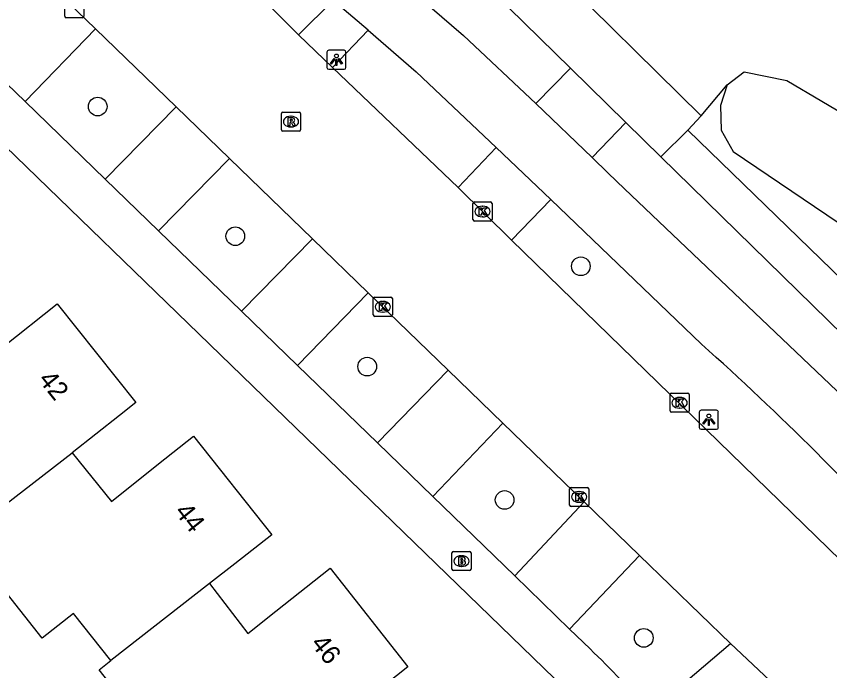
# Model space of a CAD drawing. Extents: x 157321 to 158827, y 386650 to 388532.
# Drawn here: x 157873.45 to 157916.06, y 387455 to 387489.28 of the extents above; entities that cross this region are included whole.
import ezdxf

# ---------------------------------------------------------------- set-up
doc = ezdxf.new("R2010")
doc.units = 0
for name, color, linetype in [('IMGEO_Boom', 7, 'Continuous'), ('IMGEO_Brandkraan', 7, 'Continuous'), ('IMGEO_Fietspad_gesloten', 7, 'Continuous'), ('IMGEO_Groenvoorziening', 7, 'Continuous'), ('IMGEO_Kolk', 7, 'Continuous'), ('IMGEO_Lichtpunt', 7, 'Continuous'), ('IMGEO_Loofbos', 7, 'Continuous'), ('IMGEO_Pand', 7, 'Continuous'), ('IMGEO_Pand_nummerreeks', 7, 'Continuous'), ('IMGEO_Parkeervlak_halfverhard', 7, 'Continuous'), ('IMGEO_Rijbaan_lokaal_gesloten', 7, 'Continuous'), ('IMGEO_Rioolput', 7, 'Continuous'), ('IMGEO_Voetpad_halfverhard', 7, 'Continuous'), ('IMGEO_Voetpad_open', 7, 'Continuous')]:
    doc.layers.add(name, color=color, linetype=linetype)

msp = doc.modelspace()

# ---------------------------------------------------------------- linework, layer by layer
at = {"layer": 'IMGEO_Boom'}
for centre in [(157877.711, 387484.548), (157884.92, 387477.758), (157903.019, 387476.182), (157891.829, 387470.927), (157899.026, 387463.943), (157906.315, 387456.717)]:
    msp.add_circle(centre, 0.489, dxfattribs=at)
at = {"layer": 'IMGEO_Brandkraan'}
for p, q in [((157896.265, 387460.317), (157896.265, 387461.169)), ((157896.34, 387461.243), (157897.192, 387461.243)), ((157896.753, 387461.023), (157896.778, 387461.023)), ((157897.266, 387461.169), (157897.266, 387460.317)), ((157896.776, 387460.463), (157896.751, 387460.463)), ((157897.192, 387460.243), (157896.34, 387460.243))]:
    msp.add_line(p, q, dxfattribs=at)
for points in [[(157896.265, 387460.317), (157896.265, 387461.169)], [(157896.34, 387461.243), (157897.192, 387461.243)], [(157896.613, 387460.943), (157896.613, 387460.543), (157896.826, 387460.543)], [(157896.844, 387460.943), (157896.613, 387460.943)], [(157896.792, 387460.862), (157896.738, 387460.862), (157896.738, 387460.786)], [(157897.266, 387461.169), (157897.266, 387460.317)], [(157896.738, 387460.786), (157896.791, 387460.786)], [(157896.8, 387460.71), (157896.738, 387460.71), (157896.738, 387460.629)], [(157896.738, 387460.629), (157896.8, 387460.629)], [(157897.192, 387460.243), (157896.34, 387460.243)]]:
    msp.add_lwpolyline(points, dxfattribs=at)
for centre, radius, start, end in [((157896.342, 387461.167), 0.0765, 91.552, 178.448), ((157896.342, 387461.167), 0.0765, 91.552, 178.448), ((157896.793, 387460.824), 0.0379, 267.8285, 90.9355), ((157896.848, 387460.798), 0.145, 59.4692, 91.5367), ((157896.873, 387460.845), 0.0922, 285.5137, 58.1501), ((157897.19, 387461.167), 0.0765, 1.552, 88.448), ((157897.19, 387461.167), 0.0765, 1.552, 88.448), ((157896.801, 387460.669), 0.0404, 269.8759, 90.5077), ((157896.832, 387460.794), 0.251, 268.6676, 293.5347), ((157896.878, 387460.653), 0.105, 301.3115, 78.989), ((157896.342, 387460.319), 0.0765, 181.552, 268.448), ((157896.342, 387460.319), 0.0765, 181.552, 268.448), ((157897.19, 387460.319), 0.0765, 271.552, 358.448), ((157897.19, 387460.319), 0.0765, 271.552, 358.448)]:
    msp.add_arc(centre, radius, start, end, dxfattribs=at)
for centre, major_axis, ratio, start_param, end_param in [((157896.752, 387460.743), (-0.387, 0.002), 0.722429, 4.712389, 7.853982), ((157896.777, 387460.743), (-0.39, 0.002), 0.717154, 1.570796, 4.712389)]:
    msp.add_ellipse(centre, major_axis=major_axis, ratio=ratio, start_param=start_param, end_param=end_param, dxfattribs=at)
at = {"layer": 'IMGEO_Fietspad_gesloten'}
for points in [[(157892.213, 387492.301), (157896.869, 387488.269), (157900.667, 387484.7)], [(157891.885, 387488.557), (157890.054, 387490.107)], [(157891.885, 387488.557), (157894.388, 387486.371), (157898.584, 387482.4)], [(157903.608, 387481.886), (157900.667, 387484.7)], [(157898.584, 387482.4), (157900.016, 387481.039), (157901.446, 387479.676)], [(157903.608, 387481.886), (157904.457, 387481.066), (157905.305, 387480.243), (157917.516, 387468.634)], [(157909.34, 387472.1), (157901.446, 387479.676)]]:
    msp.add_lwpolyline(points, dxfattribs=at)
msp.add_arc((157807.404, 387357.992), 153.009, 42.05065, 48.2247, dxfattribs=at)
at = {"layer": 'IMGEO_Groenvoorziening'}
msp.add_lwpolyline([(157909.326, 387484.059), (157910.689, 387485.682)], dxfattribs=at)
at = {"layer": 'IMGEO_Kolk'}
for p, q in [((157875.988, 387489.277), (157875.988, 387490.129)), ((157876.989, 387490.129), (157876.989, 387489.277)), ((157876.915, 387489.203), (157876.063, 387489.203)), ((157897.367, 387478.625), (157897.367, 387479.477)), ((157897.442, 387479.551), (157898.294, 387479.551)), ((157897.855, 387479.331), (157897.88, 387479.331)), ((157898.368, 387479.477), (157898.368, 387478.625)), ((157897.878, 387478.771), (157897.853, 387478.771)), ((157898.294, 387478.551), (157897.442, 387478.551)), ((157892.146, 387473.634), (157892.146, 387474.486)), ((157892.221, 387474.56), (157893.073, 387474.56)), ((157893.147, 387474.486), (157893.147, 387473.634)), ((157892.634, 387474.34), (157892.659, 387474.34)), ((157892.657, 387473.78), (157892.632, 387473.78)), ((157893.073, 387473.56), (157892.221, 387473.56)), ((157907.691, 387468.607), (157907.691, 387469.459)), ((157907.766, 387469.533), (157908.618, 387469.533)), ((157908.692, 387469.459), (157908.692, 387468.607)), ((157908.179, 387469.313), (157908.204, 387469.313)), ((157908.618, 387468.533), (157907.766, 387468.533)), ((157908.202, 387468.753), (157908.177, 387468.753)), ((157902.429, 387463.676), (157902.429, 387464.528)), ((157902.504, 387464.602), (157903.356, 387464.602)), ((157902.917, 387464.382), (157902.942, 387464.382)), ((157903.43, 387464.528), (157903.43, 387463.676)), ((157902.94, 387463.822), (157902.915, 387463.822)), ((157903.356, 387463.602), (157902.504, 387463.602))]:
    msp.add_line(p, q, dxfattribs=at)
for points in [[(157875.988, 387489.277), (157875.988, 387490.129)], [(157876.989, 387490.129), (157876.989, 387489.277)], [(157876.915, 387489.203), (157876.063, 387489.203)], [(157897.367, 387478.625), (157897.367, 387479.477)], [(157897.442, 387479.551), (157898.294, 387479.551)], [(157897.688, 387479.251), (157897.811, 387479.251), (157897.811, 387479.1), (157897.941, 387479.251), (157898.105, 387479.251), (157897.959, 387479.1), (157898.112, 387478.851), (157897.96, 387478.851), (157897.875, 387479.015), (157897.811, 387478.948), (157897.811, 387478.851), (157897.688, 387478.851), (157897.688, 387479.251)], [(157898.368, 387479.477), (157898.368, 387478.625)], [(157898.294, 387478.551), (157897.442, 387478.551)], [(157892.146, 387473.634), (157892.146, 387474.486)], [(157892.221, 387474.56), (157893.073, 387474.56)], [(157893.147, 387474.486), (157893.147, 387473.634)], [(157892.467, 387474.26), (157892.59, 387474.26), (157892.59, 387474.109), (157892.72, 387474.26), (157892.884, 387474.26), (157892.738, 387474.109), (157892.891, 387473.86), (157892.739, 387473.86), (157892.654, 387474.024), (157892.59, 387473.957), (157892.59, 387473.86), (157892.467, 387473.86), (157892.467, 387474.26)], [(157893.073, 387473.56), (157892.221, 387473.56)], [(157907.691, 387468.607), (157907.691, 387469.459)], [(157907.766, 387469.533), (157908.618, 387469.533)], [(157908.692, 387469.459), (157908.692, 387468.607)], [(157908.012, 387469.233), (157908.135, 387469.233), (157908.135, 387469.082), (157908.265, 387469.233), (157908.429, 387469.233), (157908.283, 387469.082), (157908.436, 387468.833), (157908.284, 387468.833), (157908.199, 387468.997), (157908.135, 387468.93), (157908.135, 387468.833), (157908.012, 387468.833), (157908.012, 387469.233)], [(157908.618, 387468.533), (157907.766, 387468.533)], [(157902.429, 387463.676), (157902.429, 387464.528)], [(157902.504, 387464.602), (157903.356, 387464.602)], [(157902.75, 387464.302), (157902.873, 387464.302), (157902.873, 387464.151), (157903.003, 387464.302), (157903.167, 387464.302), (157903.021, 387464.151), (157903.174, 387463.902), (157903.022, 387463.902), (157902.937, 387464.066), (157902.873, 387463.999), (157902.873, 387463.902), (157902.75, 387463.902), (157902.75, 387464.302)], [(157903.43, 387464.528), (157903.43, 387463.676)], [(157903.356, 387463.602), (157902.504, 387463.602)]]:
    msp.add_lwpolyline(points, dxfattribs=at)
for centre, start, end in [((157876.065, 387489.279), 181.552, 268.448), ((157876.065, 387489.279), 181.552, 268.448), ((157876.913, 387489.279), 271.552, 358.448), ((157876.913, 387489.279), 271.552, 358.448), ((157897.444, 387479.475), 91.552, 178.448), ((157897.444, 387479.475), 91.552, 178.448), ((157898.292, 387479.475), 1.552, 88.448), ((157898.292, 387479.475), 1.552, 88.448), ((157897.444, 387478.627), 181.552, 268.448), ((157897.444, 387478.627), 181.552, 268.448), ((157898.292, 387478.627), 271.552, 358.448), ((157898.292, 387478.627), 271.552, 358.448), ((157892.223, 387474.484), 91.552, 178.448), ((157892.223, 387474.484), 91.552, 178.448), ((157893.071, 387474.484), 1.552, 88.448), ((157893.071, 387474.484), 1.552, 88.448), ((157892.223, 387473.636), 181.552, 268.448), ((157892.223, 387473.636), 181.552, 268.448), ((157893.071, 387473.636), 271.552, 358.448), ((157893.071, 387473.636), 271.552, 358.448), ((157907.768, 387469.457), 91.552, 178.448), ((157907.768, 387469.457), 91.552, 178.448), ((157908.616, 387469.457), 1.552, 88.448), ((157908.616, 387469.457), 1.552, 88.448), ((157907.768, 387468.609), 181.552, 268.448), ((157907.768, 387468.609), 181.552, 268.448), ((157908.616, 387468.609), 271.552, 358.448), ((157908.616, 387468.609), 271.552, 358.448), ((157902.506, 387464.526), 91.552, 178.448), ((157902.506, 387464.526), 91.552, 178.448), ((157903.354, 387464.526), 1.552, 88.448), ((157903.354, 387464.526), 1.552, 88.448), ((157902.506, 387463.678), 181.552, 268.448), ((157902.506, 387463.678), 181.552, 268.448), ((157903.354, 387463.678), 271.552, 358.448), ((157903.354, 387463.678), 271.552, 358.448)]:
    msp.add_arc(centre, 0.0765, start, end, dxfattribs=at)
for centre, major_axis, ratio, start_param, end_param in [((157897.854, 387479.051), (-0.387, 0.002), 0.722429, 4.712389, 7.853982), ((157897.879, 387479.051), (-0.39, 0.002), 0.717154, 1.570796, 4.712389), ((157892.633, 387474.06), (-0.387, 0.002), 0.722429, 4.712389, 7.853982), ((157892.658, 387474.06), (-0.39, 0.002), 0.717154, 1.570796, 4.712389), ((157908.178, 387469.033), (-0.387, 0.002), 0.722429, 4.712389, 7.853982), ((157908.203, 387469.033), (-0.39, 0.002), 0.717154, 1.570796, 4.712389), ((157902.916, 387464.102), (-0.387, 0.002), 0.722429, 4.712389, 7.853982), ((157902.941, 387464.102), (-0.39, 0.002), 0.717154, 1.570796, 4.712389)]:
    msp.add_ellipse(centre, major_axis=major_axis, ratio=ratio, start_param=start_param, end_param=end_param, dxfattribs=at)
at = {"layer": 'IMGEO_Lichtpunt'}
for p, q in [((157889.718, 387487.4), (157889.718, 387486.593)), ((157889.718, 387487.4), (157889.718, 387486.593)), ((157890.62, 387487.495), (157889.812, 387487.495)), ((157890.62, 387487.495), (157889.812, 387487.495)), ((157890.714, 387486.593), (157890.714, 387487.4)), ((157890.714, 387486.593), (157890.714, 387487.4)), ((157889.812, 387486.499), (157890.62, 387486.499)), ((157889.812, 387486.499), (157890.62, 387486.499)), ((157909.224, 387468.545), (157909.224, 387467.738)), ((157909.224, 387468.545), (157909.224, 387467.738)), ((157910.126, 387468.64), (157909.318, 387468.64)), ((157910.126, 387468.64), (157909.318, 387468.64)), ((157910.22, 387467.738), (157910.22, 387468.545)), ((157910.22, 387467.738), (157910.22, 387468.545)), ((157909.318, 387467.644), (157910.126, 387467.644)), ((157909.318, 387467.644), (157910.126, 387467.644))]:
    msp.add_line(p, q, dxfattribs=at)
for points in [[(157890.092, 387487.064), (157890.131, 387487.036), (157889.943, 387486.774), (157889.905, 387486.801), (157890.092, 387487.064)], [(157890.194, 387487.016), (157890.241, 387487.016), (157890.241, 387486.694), (157890.194, 387486.694), (157890.194, 387487.016)], [(157890.304, 387487.036), (157890.342, 387487.063), (157890.529, 387486.801), (157890.49, 387486.773), (157890.304, 387487.036)], [(157909.598, 387468.209), (157909.637, 387468.181), (157909.449, 387467.919), (157909.411, 387467.946), (157909.598, 387468.209)], [(157909.7, 387468.161), (157909.747, 387468.161), (157909.747, 387467.839), (157909.7, 387467.839), (157909.7, 387468.161)], [(157909.81, 387468.181), (157909.848, 387468.208), (157910.035, 387467.946), (157909.996, 387467.918), (157909.81, 387468.181)]]:
    msp.add_lwpolyline(points, dxfattribs=at)
for centre in [(157890.217, 387487.198), (157909.723, 387468.343)]:
    msp.add_circle(centre, 0.0994, dxfattribs=at)
for centre, start, end in [((157889.812, 387487.4), 90, 180), ((157889.812, 387487.4), 90, 180), ((157890.62, 387487.4), 0, 90), ((157890.62, 387487.4), 0, 90), ((157889.812, 387486.593), 180, 270), ((157889.812, 387486.593), 180, 270), ((157890.62, 387486.593), 270, 0), ((157890.62, 387486.593), 270, 360), ((157909.318, 387468.545), 90, 180), ((157909.318, 387468.545), 90, 180), ((157910.126, 387468.545), 0, 90), ((157910.126, 387468.545), 0, 90), ((157909.318, 387467.738), 180, 270), ((157909.318, 387467.738), 180, 270), ((157910.126, 387467.738), 270, 0), ((157910.126, 387467.738), 270, 360)]:
    msp.add_arc(centre, 0.0946, start, end, dxfattribs=at)
at = {"layer": 'IMGEO_Loofbos'}
for points in [[(157910.689, 387485.682), (157911.565, 387486.365), (157913.814, 387485.916), (157919.306, 387482.669), (157923.372, 387481.156), (157935.544, 387477.05), (157942.355, 387474.53), (157948.457, 387471.22), (157964.756, 387462.048), (157976.58, 387455.13), (157979.394, 387453.08), (157980.825, 387451.65), (157982.615, 387449.073)], [(157910.689, 387485.682), (157910.326, 387484.599), (157910.368, 387483.317), (157911.005, 387482.202), (157916.499, 387478.471), (157919.911, 387474.608), (157929.402, 387466.712), (157931.693, 387464.535), (157934.189, 387461.533), (157935.835, 387458.059), (157937.05, 387454.914), (157938.01, 387451.564), (157938.491, 387447.402), (157938.585, 387437.383)]]:
    msp.add_lwpolyline(points, dxfattribs=at)
at = {"layer": 'IMGEO_Pand'}
for points in [[(157869.266, 387473.338), (157871.284, 387470.787), (157872.78, 387471.978), (157875.59, 387474.216), (157879.703, 387469.042), (157878.855, 387468.371), (157876.37, 387466.405)], [(157876.37, 387466.405), (157878.433, 387463.868), (157880.903, 387465.828), (157882.737, 387467.282), (157886.829, 387462.12), (157884.888, 387460.598), (157883.577, 387459.57)], [(157871.266, 387462.466), (157876.37, 387466.405)], [(157878.403, 387455.537), (157876.452, 387458.003), (157874.808, 387456.702), (157870.639, 387461.97), (157871.266, 387462.466)], [(157883.577, 387459.57), (157885.578, 387456.954), (157887.042, 387458.113), (157889.89, 387460.368), (157893.952, 387455.203), (157889.54, 387451.687), (157888.101, 387450.54)], [(157883.577, 387459.57), (157878.403, 387455.537)], [(157885.543, 387448.621), (157883.579, 387451.103), (157881.935, 387449.802), (157877.785, 387455.047), (157878.403, 387455.537)]]:
    msp.add_lwpolyline(points, dxfattribs=at)
at = {"layer": 'IMGEO_Parkeervlak_halfverhard'}
msp.add_lwpolyline([(157890.016, 387486.599), (157891.885, 387488.557)], dxfattribs=at)
at = {"layer": 'IMGEO_Rijbaan_lokaal_gesloten'}
for points in [[(157874.72, 387491.417), (157877.604, 387488.619)], [(157888.236, 387488.307), (157885.381, 387491.143)], [(157881.821, 387484.541), (157877.604, 387488.619)], [(157888.236, 387488.307), (157890.016, 387486.599)], [(157890.016, 387486.599), (157896.586, 387480.312)], [(157881.821, 387484.541), (157884.617, 387481.834)], [(157888.971, 387477.618), (157884.617, 387481.834)], [(157899.39, 387477.558), (157896.586, 387480.312)], [(157888.971, 387477.618), (157891.884, 387474.797)], [(157899.39, 387477.558), (157919.818, 387457.675)], [(157896.062, 387470.747), (157891.884, 387474.797)], [(157896.062, 387470.747), (157898.932, 387467.97)], [(157898.932, 387467.97), (157903.2, 387463.839)], [(157903.2, 387463.839), (157906.098, 387461.033)], [(157910.864, 387456.418), (157906.098, 387461.033)], [(157914.054, 387453.395), (157913.51, 387453.931), (157910.864, 387456.418)]]:
    msp.add_lwpolyline(points, dxfattribs=at)
at = {"layer": 'IMGEO_Rioolput'}
for p, q in [((157887.411, 387484.258), (157888.263, 387484.258)), ((157887.336, 387483.332), (157887.336, 387484.184)), ((157887.824, 387484.038), (157887.849, 387484.038)), ((157888.337, 387484.184), (157888.337, 387483.332)), ((157887.847, 387483.478), (157887.822, 387483.478)), ((157888.263, 387483.258), (157887.411, 387483.258))]:
    msp.add_line(p, q, dxfattribs=at)
for points in [[(157887.411, 387484.258), (157888.263, 387484.258)], [(157887.336, 387483.332), (157887.336, 387484.184)], [(157887.925, 387483.956), (157887.673, 387483.958), (157887.673, 387483.558)], [(157887.851, 387483.877), (157887.797, 387483.877), (157887.797, 387483.796)], [(157888.337, 387484.184), (157888.337, 387483.332)], [(157887.673, 387483.558), (157887.797, 387483.558), (157887.797, 387483.72), (157887.808, 387483.72)], [(157887.797, 387483.796), (157887.849, 387483.796)], [(157887.855, 387483.691), (157887.926, 387483.558), (157888.066, 387483.558), (157888.001, 387483.684)], [(157888.263, 387483.258), (157887.411, 387483.258)]]:
    msp.add_lwpolyline(points, dxfattribs=at)
for centre, radius, start, end in [((157887.413, 387484.182), 0.0765, 91.552, 178.448), ((157887.413, 387484.182), 0.0765, 91.552, 178.448), ((157888.261, 387484.182), 0.0765, 1.552, 88.448), ((157888.261, 387484.182), 0.0765, 1.552, 88.448), ((157887.857, 387483.781), 0.0964, 77.0061, 93.1865), ((157887.871, 387483.838), 0.0378, 276.6634, 79.6772), ((157887.924, 387483.846), 0.109, 350.3612, 89.416), ((157887.807, 387483.667), 0.0533, 26.0293, 88.6989), ((157887.833, 387483.985), 0.19, 274.7715, 282.9687), ((157887.922, 387483.846), 0.112, 277.5842, 350.9817), ((157887.906, 387483.631), 0.108, 29.5134, 73.7905), ((157887.413, 387483.334), 0.0765, 181.552, 268.448), ((157887.413, 387483.334), 0.0765, 181.552, 268.448), ((157888.261, 387483.334), 0.0765, 271.552, 358.448), ((157888.261, 387483.334), 0.0765, 271.552, 358.448)]:
    msp.add_arc(centre, radius, start, end, dxfattribs=at)
for centre, major_axis, ratio, start_param, end_param in [((157887.823, 387483.758), (-0.387, 0.002), 0.722429, 4.712389, 7.853982), ((157887.848, 387483.758), (-0.39, 0.002), 0.717154, 1.570796, 4.712389)]:
    msp.add_ellipse(centre, major_axis=major_axis, ratio=ratio, start_param=start_param, end_param=end_param, dxfattribs=at)
at = {"layer": 'IMGEO_Voetpad_halfverhard'}
for points in [[(157938.585, 387437.383), (157936.477, 387449.16), (157932.463, 387457.714), (157925.445, 387467.008), (157908.618, 387483.304)], [(157936.606, 387436.697), (157934.527, 387448.563), (157930.648, 387456.602), (157923.936, 387465.55), (157907.216, 387481.915)]]:
    msp.add_lwpolyline(points, dxfattribs=at)
at = {"layer": 'IMGEO_Voetpad_open'}
for points in [[(157855.004, 387537.558), (157861.771, 387530.895), (157893.149, 387500), (157909.326, 387484.059)], [(157842.827, 387511.58), (157854.778, 387500), (157901.636, 387454.595)], [(157902.476, 387486.556), (157894.394, 387494.486)], [(157890.054, 387490.107), (157888.236, 387488.307)], [(157877.604, 387488.619), (157873.909, 387484.817)], [(157873.909, 387484.817), (157870.986, 387487.615)], [(157900.667, 387484.7), (157902.476, 387486.556)], [(157902.476, 387486.556), (157905.376, 387483.711)], [(157873.909, 387484.817), (157878.107, 387480.75)], [(157878.107, 387480.75), (157881.821, 387484.541)], [(157908.618, 387483.304), (157909.326, 387484.059)], [(157905.376, 387483.711), (157903.608, 387481.886)], [(157907.216, 387481.915), (157905.376, 387483.711)], [(157907.216, 387481.915), (157908.618, 387483.304)], [(157896.586, 387480.312), (157898.584, 387482.4)], [(157884.617, 387481.834), (157880.901, 387478.042)], [(157880.901, 387478.042), (157878.107, 387480.75)], [(157901.446, 387479.676), (157899.39, 387477.558)], [(157880.901, 387478.042), (157885.243, 387473.836)], [(157885.243, 387473.836), (157888.971, 387477.618)], [(157891.884, 387474.797), (157888.177, 387470.993)], [(157888.177, 387470.993), (157885.243, 387473.836)], [(157888.177, 387470.993), (157892.361, 387466.939)], [(157892.361, 387466.939), (157896.062, 387470.747)], [(157895.275, 387464.116), (157898.932, 387467.97)], [(157895.275, 387464.116), (157892.361, 387466.939)], [(157899.56, 387459.964), (157895.275, 387464.116)], [(157903.2, 387463.839), (157899.56, 387459.964)], [(157906.098, 387461.033), (157902.43, 387457.183)], [(157902.43, 387457.183), (157899.56, 387459.964)], [(157902.43, 387457.183), (157903.501, 387456.139)], [(157906.611, 387452.809), (157910.864, 387456.418)]]:
    msp.add_lwpolyline(points, dxfattribs=at)
msp.add_arc((157876.571, 387427.871), 39.043, 39.6982, 46.3887, dxfattribs=at)

# ---------------------------------------------------------------- texts
at = {"layer": 'IMGEO_Pand_nummerreeks'}
for s, rotation, p in [('42', 308.4825, (157874.563, 387470.237)), ('44', 308.4044, (157881.699, 387463.311)), ('46', 308.1832, (157888.831, 387456.408))]:
    msp.add_text(s, height=1, rotation=rotation, dxfattribs=at).set_placement(p)

doc.saveas('drawing.dxf')
